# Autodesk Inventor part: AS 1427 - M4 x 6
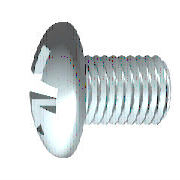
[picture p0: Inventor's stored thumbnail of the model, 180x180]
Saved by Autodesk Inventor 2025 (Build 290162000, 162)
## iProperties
Created: 2024-01
Part Number: AS 1427 - M4 x 6
Material: Acciaio, Dolce
Description: Pozidriv Viti metriche ISO
Document SubType Name: Modeling
Standard: AS 1427
Designer: R5800u
Standards Organization: AS
Language: it-IT
Size Designation: M4 x 6
Categories: <MemberInstance><Categories><Category DisplayName="Elementi di fissaggio" InternalName="e4da775c-781d-43d5-af7c-5136215cf5a6" Mnemonic="FSTN"><Category DisplayN
Density: 7.85 g/cm^3
Appearance: Semilucidato
IsCustomPart: 0
Author: R5800u
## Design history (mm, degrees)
body "Solid1"
workplane "Work Plane3"
sketch "Schizzo2"
  geometry: L1 (-5.6, 0)-(5.6, 0) reference; L2 (0, -5.6)-(0, 5.6) reference; L3 (0, 2.145)-(0, 0); L4 (0, 0)-(2.145, 0); L5 (0, 0)-(2.828, 2.828); L6 (0.495, 2.087)-(0.385, 0.645); L7 (2.087, 0.495)-(0.645, 0.385); L8 (0.495, -2.087)-(0.385, -0.645); L9 (2.087, -0.495)-(0.645, -0.385); L10 (-0.495, 2.087)-(-0.385, 0.645); L11 (-2.087, 0.495)-(-0.645, 0.385); L12 (-2.087, -0.495)-(-0.645, -0.385); L13 (-0.495, -2.087)-(-0.385, -0.645); A1 r 0.644 centre (0, 0) between (0.644, 0) and (0, 0.644); A2 r 2.145 centre (0, 0) between (2.145, 0) and (2.087, 0.495); A3 r 2.145 centre (0, 0) between (0.495, 2.087) and (0, 2.145); A4 r 2.145 centre (0, 0) between (2.087, 0.495) and (0.495, 2.087); A5 r 2.145 centre (0, 0) between (0, -2.145) and (0.495, -2.087); A6 r 2.145 centre (0, 0) between (0.495, -2.087) and (2.087, -0.495); A7 r 2.145 centre (0, 0) between (2.087, -0.495) and (2.145, 0); A8 r 2.145 centre (0, 0) between (-2.087, 0.495) and (-2.145, 0); A9 r 2.145 centre (0, 0) between (-0.495, 2.087) and (-2.087, 0.495); A10 r 2.145 centre (0, 0) between (0, 2.145) and (-0.495, 2.087); A11 r 2.145 centre (0, 0) between (-2.145, 0) and (-2.087, -0.495); A12 r 2.145 centre (0, 0) between (-2.087, -0.495) and (-0.495, -2.087); A13 r 2.145 centre (0, 0) between (-0.495, -2.087) and (0, -2.145); A14 r 0.751 centre (0, 0) between (0.751, 0) and (0, 0.751); A15 r 0.242 centre (0.626, 0.626) between (0.385, 0.645) and (0.645, 0.385); A16 r 0.242 centre (0.626, -0.626) between (0.645, -0.385) and (0.385, -0.645); A17 r 0.242 centre (-0.626, 0.626) between (-0.645, 0.385) and (-0.385, 0.645); A18 r 0.242 centre (-0.626, -0.626) between (-0.385, -0.645) and (-0.645, -0.385); 1 further point
  constraints: 38 point on circle, 22 end point, 19 symmetric about line, 18 centre point, 4 coincident, 3 collinear, 3 point on line, 3 tangent, 1 perpendicular, 21 other
  dimensions: "d4" = 45 deg angle of L5 L4; "d5" = 1.287 diameter of A1 (= 0.3 x SDM); "d6" = 4.29 diameter of A4 (= SDM); "d7" = 0.495 distance from line of L6.start L3 (= 0.5 x SBR); "d14" = 1.5015 diameter of A14 (= 0.35 x SDM)
extrude "Intaglio" join sketch "Schizzo2" taper "d15" = 5 deg; stored distance "d54" = 10
revolve "Taglio" stored, may be unused: angle "d56" = 90 deg
revolve "Corpo" stored, may be unused: angle "d18" = 90 deg
workplane "Work Plane1"
sketch "Schizzo1"
  geometry: L1 (6, 0)-(6, 2); L2 (6, 2)-(1.4, 2); L3 (3.962, 5.08)-(3.962, 5.08); L4 (-2.66, 0)-(-2.66, 4); L5 (-2.334, 1.983)-(-1.654, 1.643); L6 (-1.654, 1.643)-(-0.78, 0); L7 (-0.78, 0)-(6, 0); L8 (-4.817, 0)-(7.803, 0) reference; L9 (0, -1.016)-(0, 6.096) reference; L10 (-2.334, 1.983)-(-2.66, 2.145); L11 (-1.197, 4)-(-2.66, 4); L12 (-1.197, 4)-(0, 4); L13 (0, 4)-(0, 1.785); L14 (0, 1.785)-(0.971, 1.785); L15 (0.971, 1.785)-(1.4, 2); L16 (1.4, 2)-(0, 2); A1 r 6.2 centre (3.54, 0) between (-1.197, 4) and (-2.66, 0)
  constraints: 28 end point, 5 point on line, 4 collinear, 4 point on circle, 3 parallel, 2 perpendicular, 1 centre point, 1 horizontal, 1 tangent
  dimensions: "d1" = 4 diameter of L2 L7 (= GD); "d2" = 1.88 distance from line of L6.end L4 (= STI); "d11" = 4.29 diameter of L10.end L7 (= SDM); "d12" = 62 deg angle of L6 L7; "d13" = 26.5 deg angle of L5 L7; "d17" = 8 diameter of L12.end L7 (= KOD); "d19" = 0.01 deg angle of L12 L7 (= KEWI); "d20" = 2.66 distance between parallel lines of L4 L13 (= KOH); "d21" = 6.2 radius of A1 (= KR); "d23" = 3.5705 diameter of L14 L7 (= BDM); "d24" = 4.6 distance of L1.end L2.end (= GEL); "d25" = 0.42941 horizontal distance of L14.end L2.end (= GAL); "d28" = 6 distance between parallel lines of L1 L13 (= NLG)
fillet "Raccordo1" dims "d29" = 1.6 (= RR)
fillet "Raccordo2" dims "d16" = 0.198 (= 0.2 x SBR)
feature "Filettatura" dims "d8" = 4.6 (= GEL), "d9" = 0
chamfer "Smusso1" distance "d26" = 0.42941 (= -0.5 x SPD + 0.5 x GD); stored, may be unused: second distance "d27" = 0.42952 (computed from GUL), angle "d78" = 45 deg
other parameters: "GD" = 4 (= NND) [user parameter; used in 2 equation terms], "NLG" = 6 [user parameter; used in 1 equation term], "GEL" = 4.6 [user parameter; used in 2 equation terms], "KOD" = 8 [user parameter; used in 1 equation term], "KOH" = 2.66 [user parameter; used in 2 equation terms], "SDM" = 4.29 [user parameter; used in 4 equation terms], "STI" = 1.88 [user parameter; used in 1 equation term], "SBR" = 0.99 [user parameter; used in 2 equation terms], "GAL" = 0.42941 (= 0.61345 x PTC) [user parameter; used in 1 equation term], "SPD" = 3.14117 (= NND - 1.2269 x PTC) [user parameter; used in 1 equation term], "KEWI" = 0.01 deg [user parameter; used in 1 equation term], "d3" = -2.66 (= -KOH), "d10" = 0, "KR" = 6.2 [user parameter; used in 1 equation term], "BDM" = 3.5705 [user parameter; used in 1 equation term], "GUL" = 0.42941 (= 0.61345 x PTC) [user parameter; used in 1 equation term], "RR" = 1.6 [user parameter; used in 1 equation term], "d79" = 0, "d80" = 0, "PTC" = 0.7 [user parameter; used in 5 equation terms], "THREADDIA" = 4 [user parameter; used in 1 equation term], "TOA" = 30 deg [user parameter], "TPU" = 14.28571 (computed from PTC) [user parameter], "NND" = 4 [user parameter; used in 2 equation terms], "GD1" = 3.14117 (= THREADDIA - 1.2269 x PTC) [user parameter]
